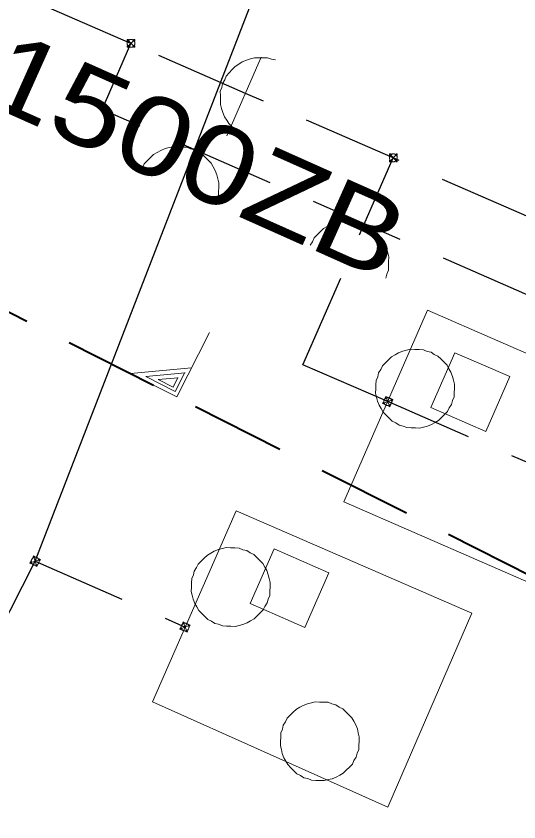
# Model space of a CAD drawing. Extents: x -740851 to -738888, y -1041382 to -1040235.
# Drawn here: x -739031.22 to -739024.84, y -1041331.21 to -1041320.97 of the extents above; entities that cross this region are included whole.
import ezdxf

# ---------------------------------------------------------------- set-up
doc = ezdxf.new("R2010")
doc.units = 0
doc.header["$LTSCALE"] = 0.4
doc.linetypes.add('MEDIUM_DASHED', pattern=[4.5, 3, -1.5])
doc.layers.add('18', color=7, linetype='Continuous', lineweight=13)
doc.layers.add('8', color=7, linetype='Continuous', lineweight=13)

msp = doc.modelspace()

# ---------------------------------------------------------------- linework, layer by layer
at = {"layer": '18', "linetype": 'MEDIUM_DASHED', "lineweight": 40}
msp.add_lwpolyline([(-739015.025, -1041332.979), (-739045.2, -1041317.71), (-739098.28, -1041294.28)], dxfattribs=at)
at = {"layer": '18'}
for points in [[(-739028.77, -1041324.992), (-739029.185, -1041325.812), (-739029.77, -1041325.515), (-739028.998, -1041325.442)], [(-739029.082, -1041325.502), (-739029.203, -1041325.741), (-739029.577, -1041325.552), (-739029.078, -1041325.504)], [(-739029.169, -1041325.566), (-739029.229, -1041325.686), (-739029.421, -1041325.589), (-739029.165, -1041325.568)]]:
    msp.add_lwpolyline(points, dxfattribs=at)
at = {"layer": '8'}
for p, q in [((-739029.815, -1041321.369), (-739029.715, -1041321.269)), ((-739029.815, -1041321.269), (-739029.715, -1041321.369)), ((-739029.815, -1041321.269), (-739029.815, -1041321.289)), ((-739029.815, -1041321.269), (-739029.795, -1041321.269)), ((-739029.715, -1041321.269), (-739029.735, -1041321.269)), ((-739029.715, -1041321.269), (-739029.715, -1041321.289)), ((-739029.815, -1041321.369), (-739029.815, -1041321.349)), ((-739029.815, -1041321.369), (-739029.795, -1041321.369)), ((-739029.715, -1041321.369), (-739029.735, -1041321.369)), ((-739029.715, -1041321.369), (-739029.715, -1041321.349)), ((-739028.548, -1041322.494), (-739028.112, -1041321.494)), ((-739026.484, -1041322.823), (-739026.384, -1041322.723)), ((-739026.484, -1041322.723), (-739026.384, -1041322.823)), ((-739026.484, -1041322.723), (-739026.484, -1041322.743)), ((-739026.484, -1041322.723), (-739026.464, -1041322.723)), ((-739026.384, -1041322.723), (-739026.404, -1041322.723)), ((-739026.384, -1041322.723), (-739026.384, -1041322.743)), ((-739026.484, -1041322.823), (-739026.484, -1041322.803)), ((-739026.484, -1041322.823), (-739026.464, -1041322.823)), ((-739026.384, -1041322.823), (-739026.404, -1041322.823)), ((-739026.384, -1041322.823), (-739026.384, -1041322.803)), ((-739026.53, -1041325.804), (-739026.538, -1041325.823)), ((-739026.53, -1041325.804), (-739026.479, -1041325.936)), ((-739026.53, -1041325.804), (-739026.512, -1041325.812)), ((-739026.439, -1041325.844), (-739026.457, -1041325.836)), ((-739026.57, -1041325.896), (-739026.439, -1041325.844)), ((-739026.57, -1041325.896), (-739026.562, -1041325.878)), ((-739026.57, -1041325.896), (-739026.552, -1041325.904)), ((-739026.479, -1041325.936), (-739026.497, -1041325.928)), ((-739026.479, -1041325.936), (-739026.471, -1041325.918)), ((-739026.439, -1041325.844), (-739026.447, -1041325.863)), ((-739031.048, -1041327.92), (-739030.913, -1041327.877)), ((-739031.002, -1041327.831), (-739031.011, -1041327.849)), ((-739030.959, -1041327.966), (-739031.002, -1041327.831)), ((-739031.002, -1041327.831), (-739030.985, -1041327.841)), ((-739030.913, -1041327.877), (-739030.931, -1041327.868)), ((-739030.913, -1041327.877), (-739030.922, -1041327.895)), ((-739031.048, -1041327.92), (-739031.039, -1041327.903)), ((-739031.048, -1041327.92), (-739031.03, -1041327.93)), ((-739030.959, -1041327.966), (-739030.977, -1041327.957)), ((-739030.959, -1041327.966), (-739030.95, -1041327.948)), ((-739029.012, -1041328.71), (-739029.145, -1041328.76)), ((-739029.104, -1041328.669), (-739029.112, -1041328.687)), ((-739029.053, -1041328.801), (-739029.104, -1041328.669)), ((-739029.104, -1041328.669), (-739029.085, -1041328.677)), ((-739029.012, -1041328.71), (-739029.031, -1041328.702)), ((-739029.012, -1041328.71), (-739029.021, -1041328.728)), ((-739029.145, -1041328.76), (-739029.136, -1041328.742)), ((-739029.145, -1041328.76), (-739029.126, -1041328.769)), ((-739029.053, -1041328.801), (-739029.072, -1041328.793)), ((-739029.053, -1041328.801), (-739029.045, -1041328.783))]:
    msp.add_line(p, q, dxfattribs=at)
at = {"layer": '8', "linetype": 'MEDIUM_DASHED', "lineweight": 25}
for p, q in [((-739028.313, -1041321.954), (-739029.766, -1041321.32)), ((-739026.435, -1041322.774), (-739028.313, -1041321.954)), ((-739023.828, -1041327.038), (-739026.506, -1041325.871)), ((-739030.98, -1041327.9), (-739029.077, -1041328.735))]:
    msp.add_line(p, q, dxfattribs=at)
at = {"layer": '8', "lineweight": 25}
for points in [[(-739030.98, -1041327.9), (-739026.78, -1041317.04), (-739010.3, -1041323.4), (-739009.27, -1041324.07), (-739006.93, -1041324.54), (-738999.34, -1041319.61), (-738973.83, -1041324.2), (-738967.89, -1041326.96), (-738912.6, -1041336.12), (-738898.9, -1041324.07), (-738902.59, -1041288.03), (-738903.44, -1041282.07), (-738902.27, -1041277.31), (-738903.16, -1041268.86), (-738902.4, -1041255.6), (-738900.82, -1041237.82), (-738900.46, -1041231.31), (-738900.36, -1041226.7), (-738895.11, -1041221.55), (-738893.11, -1041208.58), (-738893.07, -1041208.11), (-738892.71, -1041202.04)], [(-739033.31, -1041334.18), (-739031.62, -1041329.15), (-739030.98, -1041327.9)]]:
    msp.add_lwpolyline(points, dxfattribs=at)
at = {"layer": '8', "linetype": 'MEDIUM_DASHED', "lineweight": 25}
for points in [[(-739029.766, -1041321.32), (-739082.235, -1041298.419), (-739128.51, -1041277.178), (-739131.478, -1041275.908), (-739142.38, -1041271.06)], [(-739023.322, -1041325.878), (-739023.048, -1041325.249), (-739030.132, -1041322.158), (-739029.766, -1041321.32)], [(-739026.506, -1041325.871), (-739027.582, -1041325.402), (-739026.435, -1041322.774)], [(-738998.96, -1041334.03), (-739001.617, -1041333.611), (-739026.435, -1041322.774)]]:
    msp.add_lwpolyline(points, dxfattribs=at)
at = {"layer": '8'}
for points in [[(-739029.715, -1041321.319), (-739029.715, -1041321.314), (-739029.716, -1041321.309), (-739029.717, -1041321.304), (-739029.719, -1041321.299), (-739029.722, -1041321.294), (-739029.725, -1041321.29), (-739029.728, -1041321.286), (-739029.732, -1041321.282), (-739029.736, -1041321.279), (-739029.74, -1041321.276), (-739029.745, -1041321.273), (-739029.75, -1041321.271), (-739029.755, -1041321.27), (-739029.76, -1041321.269), (-739029.765, -1041321.269), (-739029.77, -1041321.269), (-739029.775, -1041321.27), (-739029.78, -1041321.271), (-739029.785, -1041321.273), (-739029.79, -1041321.276), (-739029.794, -1041321.279), (-739029.798, -1041321.282), (-739029.802, -1041321.286), (-739029.805, -1041321.29), (-739029.808, -1041321.294), (-739029.811, -1041321.299), (-739029.813, -1041321.304), (-739029.814, -1041321.309), (-739029.815, -1041321.314), (-739029.815, -1041321.319), (-739029.815, -1041321.324), (-739029.814, -1041321.329), (-739029.813, -1041321.334), (-739029.811, -1041321.339), (-739029.808, -1041321.344), (-739029.805, -1041321.348), (-739029.802, -1041321.352), (-739029.798, -1041321.356), (-739029.794, -1041321.359), (-739029.79, -1041321.362), (-739029.785, -1041321.365), (-739029.78, -1041321.367), (-739029.775, -1041321.368), (-739029.77, -1041321.369), (-739029.765, -1041321.369), (-739029.76, -1041321.369), (-739029.755, -1041321.368), (-739029.75, -1041321.367), (-739029.745, -1041321.365), (-739029.74, -1041321.362), (-739029.736, -1041321.359), (-739029.732, -1041321.356), (-739029.728, -1041321.352), (-739029.725, -1041321.348), (-739029.722, -1041321.344), (-739029.719, -1041321.339), (-739029.717, -1041321.334), (-739029.716, -1041321.329), (-739029.715, -1041321.324)], [(-739026.384, -1041322.773), (-739026.384, -1041322.768), (-739026.385, -1041322.763), (-739026.386, -1041322.758), (-739026.388, -1041322.753), (-739026.391, -1041322.748), (-739026.394, -1041322.744), (-739026.397, -1041322.74), (-739026.401, -1041322.736), (-739026.405, -1041322.733), (-739026.409, -1041322.73), (-739026.414, -1041322.727), (-739026.419, -1041322.725), (-739026.424, -1041322.724), (-739026.429, -1041322.723), (-739026.434, -1041322.723), (-739026.439, -1041322.723), (-739026.444, -1041322.724), (-739026.449, -1041322.725), (-739026.454, -1041322.727), (-739026.459, -1041322.73), (-739026.463, -1041322.733), (-739026.467, -1041322.736), (-739026.471, -1041322.74), (-739026.474, -1041322.744), (-739026.477, -1041322.748), (-739026.48, -1041322.753), (-739026.482, -1041322.758), (-739026.483, -1041322.763), (-739026.484, -1041322.768), (-739026.484, -1041322.773), (-739026.484, -1041322.778), (-739026.483, -1041322.783), (-739026.482, -1041322.788), (-739026.48, -1041322.793), (-739026.477, -1041322.798), (-739026.474, -1041322.802), (-739026.471, -1041322.806), (-739026.467, -1041322.81), (-739026.463, -1041322.813), (-739026.459, -1041322.816), (-739026.454, -1041322.819), (-739026.449, -1041322.821), (-739026.444, -1041322.822), (-739026.439, -1041322.823), (-739026.434, -1041322.823), (-739026.429, -1041322.823), (-739026.424, -1041322.822), (-739026.419, -1041322.821), (-739026.414, -1041322.819), (-739026.409, -1041322.816), (-739026.405, -1041322.813), (-739026.401, -1041322.81), (-739026.397, -1041322.806), (-739026.394, -1041322.802), (-739026.391, -1041322.798), (-739026.388, -1041322.793), (-739026.386, -1041322.788), (-739026.385, -1041322.783), (-739026.384, -1041322.778)], [(-739026, -1041324.71), (-739020.645, -1041327.046), (-739021.706, -1041329.48), (-739027.061, -1041327.144)], [(-739025.956, -1041325.242), (-739026.007, -1041325.232), (-739026.053, -1041325.211), (-739026.108, -1041325.21), (-739026.162, -1041325.208), (-739026.217, -1041325.206), (-739026.266, -1041325.218), (-739026.315, -1041325.23), (-739026.368, -1041325.251), (-739026.412, -1041325.276), (-739026.456, -1041325.301), (-739026.495, -1041325.339), (-739026.534, -1041325.377), (-739026.573, -1041325.415), (-739026.593, -1041325.462), (-739026.623, -1041325.504), (-739026.633, -1041325.555), (-739026.654, -1041325.601), (-739026.655, -1041325.655), (-739026.657, -1041325.71), (-739026.659, -1041325.764), (-739026.647, -1041325.814), (-739026.635, -1041325.863), (-739026.614, -1041325.916), (-739026.589, -1041325.96), (-739026.564, -1041326.004), (-739026.526, -1041326.043), (-739026.488, -1041326.082), (-739026.45, -1041326.12), (-739026.403, -1041326.141), (-739026.361, -1041326.17), (-739026.31, -1041326.181), (-739026.264, -1041326.201), (-739026.21, -1041326.203), (-739026.155, -1041326.205), (-739026.101, -1041326.206), (-739026.051, -1041326.195), (-739026.002, -1041326.183), (-739025.949, -1041326.162), (-739025.905, -1041326.137), (-739025.861, -1041326.112), (-739025.822, -1041326.074), (-739025.783, -1041326.036), (-739025.745, -1041325.997), (-739025.724, -1041325.951), (-739025.695, -1041325.909), (-739025.684, -1041325.858), (-739025.664, -1041325.812), (-739025.662, -1041325.757), (-739025.66, -1041325.703), (-739025.659, -1041325.648), (-739025.67, -1041325.599), (-739025.682, -1041325.55), (-739025.703, -1041325.497), (-739025.728, -1041325.453), (-739025.753, -1041325.409), (-739025.791, -1041325.37), (-739025.829, -1041325.331), (-739025.868, -1041325.292), (-739025.914, -1041325.272)], [(-739025.957, -1041325.946), (-739025.261, -1041326.25), (-739024.957, -1041325.553), (-739025.654, -1041325.25)], [(-739026.459, -1041325.89), (-739026.457, -1041325.886), (-739026.456, -1041325.881), (-739026.455, -1041325.876), (-739026.454, -1041325.87), (-739026.455, -1041325.864), (-739026.456, -1041325.86), (-739026.457, -1041325.855), (-739026.46, -1041325.849), (-739026.462, -1041325.845), (-739026.464, -1041325.841), (-739026.468, -1041325.836), (-739026.472, -1041325.832), (-739026.476, -1041325.829), (-739026.48, -1041325.826), (-739026.485, -1041325.824), (-739026.489, -1041325.822), (-739026.494, -1041325.821), (-739026.499, -1041325.82), (-739026.505, -1041325.82), (-739026.51, -1041325.821), (-739026.515, -1041325.822), (-739026.52, -1041325.823), (-739026.525, -1041325.825), (-739026.53, -1041325.828), (-739026.534, -1041325.83), (-739026.539, -1041325.833), (-739026.543, -1041325.837), (-739026.546, -1041325.841), (-739026.548, -1041325.846), (-739026.55, -1041325.85), (-739026.552, -1041325.855), (-739026.553, -1041325.86), (-739026.555, -1041325.865), (-739026.555, -1041325.87), (-739026.554, -1041325.876), (-739026.553, -1041325.881), (-739026.552, -1041325.886), (-739026.55, -1041325.891), (-739026.547, -1041325.895), (-739026.545, -1041325.9), (-739026.541, -1041325.904), (-739026.538, -1041325.908), (-739026.533, -1041325.911), (-739026.529, -1041325.914), (-739026.525, -1041325.916), (-739026.52, -1041325.918), (-739026.515, -1041325.919), (-739026.51, -1041325.92), (-739026.505, -1041325.92), (-739026.499, -1041325.92), (-739026.494, -1041325.918), (-739026.489, -1041325.917), (-739026.484, -1041325.915), (-739026.48, -1041325.913), (-739026.475, -1041325.91), (-739026.47, -1041325.907), (-739026.467, -1041325.903), (-739026.464, -1041325.899), (-739026.461, -1041325.895)], [(-739028.43, -1041327.26), (-739025.44, -1041328.56), (-739026.503, -1041331.023), (-739029.492, -1041329.687)], [(-739028.295, -1041327.763), (-739028.346, -1041327.752), (-739028.392, -1041327.731), (-739028.446, -1041327.73), (-739028.501, -1041327.728), (-739028.555, -1041327.726), (-739028.605, -1041327.738), (-739028.654, -1041327.749), (-739028.707, -1041327.77), (-739028.751, -1041327.795), (-739028.795, -1041327.82), (-739028.834, -1041327.858), (-739028.873, -1041327.896), (-739028.912, -1041327.934), (-739028.932, -1041327.98), (-739028.962, -1041328.023), (-739028.973, -1041328.073), (-739028.993, -1041328.119), (-739028.995, -1041328.174), (-739028.997, -1041328.228), (-739028.999, -1041328.283), (-739028.987, -1041328.332), (-739028.976, -1041328.381), (-739028.955, -1041328.435), (-739028.93, -1041328.479), (-739028.905, -1041328.523), (-739028.867, -1041328.562), (-739028.829, -1041328.6), (-739028.791, -1041328.639), (-739028.744, -1041328.66), (-739028.702, -1041328.689), (-739028.652, -1041328.7), (-739028.605, -1041328.721), (-739028.551, -1041328.722), (-739028.496, -1041328.724), (-739028.442, -1041328.726), (-739028.393, -1041328.714), (-739028.343, -1041328.703), (-739028.29, -1041328.682), (-739028.246, -1041328.657), (-739028.202, -1041328.632), (-739028.163, -1041328.594), (-739028.124, -1041328.556), (-739028.085, -1041328.518), (-739028.065, -1041328.472), (-739028.035, -1041328.429), (-739028.024, -1041328.379), (-739028.004, -1041328.333), (-739028.002, -1041328.278), (-739028, -1041328.224), (-739027.999, -1041328.169), (-739028.01, -1041328.12), (-739028.022, -1041328.071), (-739028.042, -1041328.017), (-739028.067, -1041327.973), (-739028.092, -1041327.929), (-739028.13, -1041327.89), (-739028.169, -1041327.852), (-739028.207, -1041327.813), (-739028.253, -1041327.792)], [(-739028.252, -1041328.437), (-739027.557, -1041328.742), (-739027.252, -1041328.047), (-739027.947, -1041327.742)], [(-739030.958, -1041327.854), (-739030.962, -1041327.852), (-739030.967, -1041327.851), (-739030.972, -1041327.849), (-739030.977, -1041327.849), (-739030.983, -1041327.849), (-739030.988, -1041327.85), (-739030.993, -1041327.851), (-739030.999, -1041327.853), (-739031.003, -1041327.855), (-739031.008, -1041327.857), (-739031.012, -1041327.86), (-739031.017, -1041327.864), (-739031.02, -1041327.868), (-739031.023, -1041327.872), (-739031.025, -1041327.876), (-739031.027, -1041327.88), (-739031.029, -1041327.885), (-739031.03, -1041327.89), (-739031.031, -1041327.896), (-739031.03, -1041327.901), (-739031.029, -1041327.906), (-739031.029, -1041327.911), (-739031.027, -1041327.917), (-739031.025, -1041327.921), (-739031.022, -1041327.926), (-739031.019, -1041327.931), (-739031.016, -1041327.935), (-739031.012, -1041327.938), (-739031.008, -1041327.941), (-739031.003, -1041327.943), (-739030.999, -1041327.946), (-739030.994, -1041327.947), (-739030.989, -1041327.948), (-739030.984, -1041327.949), (-739030.978, -1041327.948), (-739030.973, -1041327.948), (-739030.968, -1041327.947), (-739030.963, -1041327.945), (-739030.958, -1041327.943), (-739030.954, -1041327.941), (-739030.949, -1041327.938), (-739030.945, -1041327.934), (-739030.942, -1041327.93), (-739030.938, -1041327.926), (-739030.936, -1041327.922), (-739030.934, -1041327.917), (-739030.932, -1041327.912), (-739030.931, -1041327.907), (-739030.931, -1041327.902), (-739030.931, -1041327.896), (-739030.932, -1041327.891), (-739030.933, -1041327.886), (-739030.934, -1041327.881), (-739030.937, -1041327.876), (-739030.939, -1041327.872), (-739030.942, -1041327.867), (-739030.945, -1041327.863), (-739030.949, -1041327.86), (-739030.953, -1041327.857)], [(-739029.124, -1041328.715), (-739029.126, -1041328.719), (-739029.127, -1041328.724), (-739029.128, -1041328.729), (-739029.129, -1041328.735), (-739029.128, -1041328.74), (-739029.127, -1041328.745), (-739029.126, -1041328.75), (-739029.124, -1041328.756), (-739029.121, -1041328.76), (-739029.119, -1041328.764), (-739029.116, -1041328.769), (-739029.112, -1041328.773), (-739029.108, -1041328.776), (-739029.104, -1041328.779), (-739029.099, -1041328.781), (-739029.094, -1041328.783), (-739029.089, -1041328.784), (-739029.084, -1041328.785), (-739029.079, -1041328.785), (-739029.073, -1041328.785), (-739029.068, -1041328.784), (-739029.064, -1041328.782), (-739029.058, -1041328.78), (-739029.054, -1041328.778), (-739029.049, -1041328.776), (-739029.045, -1041328.772), (-739029.041, -1041328.768), (-739029.038, -1041328.764), (-739029.035, -1041328.76), (-739029.033, -1041328.756), (-739029.031, -1041328.751), (-739029.03, -1041328.746), (-739029.029, -1041328.741), (-739029.028, -1041328.736), (-739029.029, -1041328.73), (-739029.03, -1041328.725), (-739029.031, -1041328.72), (-739029.033, -1041328.715), (-739029.036, -1041328.711), (-739029.038, -1041328.706), (-739029.041, -1041328.701), (-739029.045, -1041328.698), (-739029.049, -1041328.695), (-739029.054, -1041328.692), (-739029.058, -1041328.69), (-739029.063, -1041328.688), (-739029.068, -1041328.686), (-739029.073, -1041328.685), (-739029.078, -1041328.685), (-739029.084, -1041328.686), (-739029.089, -1041328.687), (-739029.094, -1041328.688), (-739029.099, -1041328.69), (-739029.103, -1041328.692), (-739029.108, -1041328.695), (-739029.112, -1041328.698), (-739029.116, -1041328.702), (-739029.119, -1041328.706), (-739029.122, -1041328.71)], [(-739027.165, -1041329.723), (-739027.215, -1041329.712), (-739027.262, -1041329.691), (-739027.316, -1041329.69), (-739027.371, -1041329.688), (-739027.425, -1041329.686), (-739027.474, -1041329.698), (-739027.524, -1041329.709), (-739027.577, -1041329.73), (-739027.621, -1041329.755), (-739027.665, -1041329.78), (-739027.704, -1041329.818), (-739027.743, -1041329.856), (-739027.781, -1041329.894), (-739027.802, -1041329.941), (-739027.831, -1041329.983), (-739027.842, -1041330.033), (-739027.863, -1041330.08), (-739027.864, -1041330.134), (-739027.866, -1041330.189), (-739027.868, -1041330.243), (-739027.856, -1041330.292), (-739027.845, -1041330.342), (-739027.824, -1041330.395), (-739027.799, -1041330.439), (-739027.774, -1041330.483), (-739027.736, -1041330.522), (-739027.698, -1041330.561), (-739027.66, -1041330.6), (-739027.613, -1041330.62), (-739027.571, -1041330.649), (-739027.521, -1041330.66), (-739027.474, -1041330.681), (-739027.42, -1041330.683), (-739027.365, -1041330.684), (-739027.311, -1041330.686), (-739027.262, -1041330.674), (-739027.212, -1041330.663), (-739027.159, -1041330.642), (-739027.115, -1041330.617), (-739027.071, -1041330.592), (-739027.032, -1041330.554), (-739026.993, -1041330.516), (-739026.954, -1041330.478), (-739026.934, -1041330.431), (-739026.905, -1041330.389), (-739026.894, -1041330.339), (-739026.873, -1041330.292), (-739026.871, -1041330.238), (-739026.87, -1041330.183), (-739026.868, -1041330.129), (-739026.88, -1041330.08), (-739026.891, -1041330.03), (-739026.912, -1041329.977), (-739026.937, -1041329.933), (-739026.962, -1041329.889), (-739027, -1041329.85), (-739027.038, -1041329.811), (-739027.076, -1041329.773), (-739027.123, -1041329.752)]]:
    msp.add_lwpolyline(points, close=True, dxfattribs=at)
for points in [[(-739027.929, -1041321.529), (-739027.981, -1041321.52), (-739028.03, -1041321.501), (-739028.086, -1041321.502), (-739028.142, -1041321.503), (-739028.198, -1041321.503), (-739028.248, -1041321.517), (-739028.299, -1041321.532), (-739028.353, -1041321.555), (-739028.397, -1041321.583), (-739028.441, -1041321.611), (-739028.479, -1041321.652), (-739028.517, -1041321.693), (-739028.556, -1041321.734), (-739028.574, -1041321.782), (-739028.603, -1041321.827), (-739028.612, -1041321.88), (-739028.631, -1041321.928), (-739028.63, -1041321.984), (-739028.63, -1041322.041), (-739028.629, -1041322.097), (-739028.615, -1041322.147), (-739028.601, -1041322.197), (-739028.577, -1041322.251), (-739028.549, -1041322.295), (-739028.522, -1041322.339), (-739028.481, -1041322.378), (-739028.439, -1041322.416), (-739028.398, -1041322.454), (-739028.35, -1041322.473), (-739028.305, -1041322.501)], [(-739028.687, -1041323.361), (-739028.675, -1041323.309), (-739028.654, -1041323.26), (-739028.652, -1041323.204), (-739028.651, -1041323.147), (-739028.649, -1041323.091), (-739028.661, -1041323.04), (-739028.673, -1041322.989), (-739028.695, -1041322.933), (-739028.721, -1041322.888), (-739028.747, -1041322.842), (-739028.786, -1041322.802), (-739028.826, -1041322.762), (-739028.866, -1041322.721), (-739028.914, -1041322.7), (-739028.958, -1041322.67), (-739029.01, -1041322.658), (-739029.058, -1041322.637), (-739029.115, -1041322.636), (-739029.171, -1041322.634), (-739029.228, -1041322.632), (-739029.279, -1041322.644), (-739029.33, -1041322.656), (-739029.385, -1041322.678), (-739029.431, -1041322.704), (-739029.477, -1041322.73), (-739029.517, -1041322.769), (-739029.557, -1041322.809), (-739029.597, -1041322.849), (-739029.618, -1041322.897), (-739029.649, -1041322.941)], [(-739026.53, -1041324.303), (-739026.518, -1041324.251), (-739026.497, -1041324.202), (-739026.495, -1041324.146), (-739026.494, -1041324.089), (-739026.492, -1041324.033), (-739026.504, -1041323.982), (-739026.516, -1041323.931), (-739026.538, -1041323.875), (-739026.564, -1041323.83), (-739026.59, -1041323.784), (-739026.629, -1041323.744), (-739026.669, -1041323.704), (-739026.709, -1041323.663), (-739026.757, -1041323.642), (-739026.801, -1041323.612), (-739026.853, -1041323.6), (-739026.901, -1041323.579), (-739026.958, -1041323.578), (-739027.014, -1041323.576), (-739027.071, -1041323.574), (-739027.122, -1041323.586), (-739027.173, -1041323.598), (-739027.228, -1041323.62), (-739027.274, -1041323.646), (-739027.32, -1041323.672), (-739027.36, -1041323.711), (-739027.4, -1041323.751), (-739027.44, -1041323.791), (-739027.461, -1041323.839), (-739027.492, -1041323.883)]]:
    msp.add_lwpolyline(points, dxfattribs=at)

# ---------------------------------------------------------------- texts
at = {"layer": '18', "width": 1.2}
msp.add_text('1500ZB', height=1, rotation=335.913, dxfattribs=at).set_placement((-739031.694, -1041322.046))

doc.saveas('drawing.dxf')
